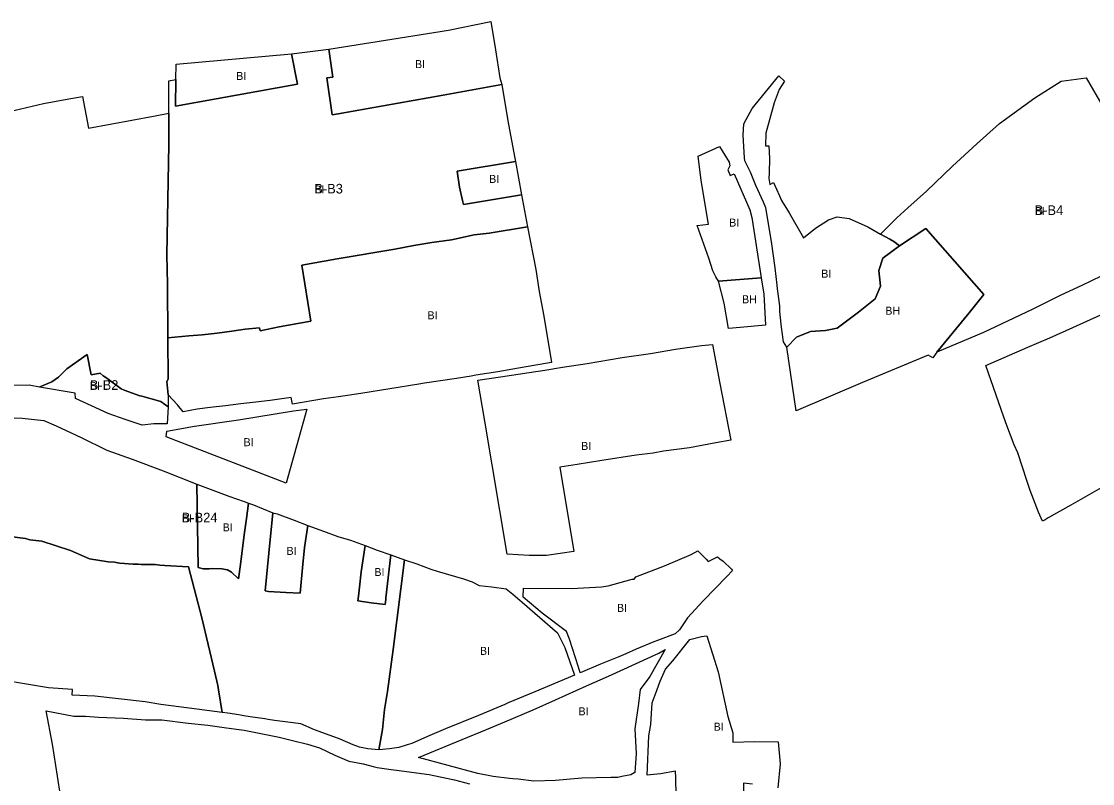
# Model space of a CAD drawing. Extents: x -532081 to -530154, y -1179372 to -1177675.
# Drawn here: x -531512 to -530843, y -1178449 to -1177973 of the extents above; entities that cross this region are included whole.
import ezdxf

# ---------------------------------------------------------------- set-up
doc = ezdxf.new("R2010")
doc.units = 0
for name, color, linetype in [('90030013', 7, 'Continuous'), ('90040013', 7, 'Continuous'), ('90040023', 7, 'Continuous'), ('ID_navrh', 7, 'Continuous')]:
    doc.layers.add(name, color=color, linetype=linetype)

msp = doc.modelspace()

# ---------------------------------------------------------------- linework, layer by layer
at = {"layer": '90030013'}
for points in [[(-530940.69, -1178179.99), (-530943.19, -1178183.38), (-530946.02, -1178181.86), (-530987.13, -1178198.87), (-531028.46, -1178216.55), (-531034.33, -1178176.84), (-531028.24, -1178170.51), (-531019.54, -1178167.02), (-531010.19, -1178166.36), (-531002.79, -1178164.84), (-530989.52, -1178155.02), (-530979.08, -1178146.51), (-530975.82, -1178138.65), (-530976.9, -1178128.84), (-530974.29, -1178121.2), (-530964.07, -1178113.56), (-530947.55, -1178102.59), (-530911.33, -1178143.87), (-530920.54, -1178155.27)], [(-531063.56, -1178164.47), (-531070.77, -1178165.22), (-531073.51, -1178149.25), (-531076.99, -1178135.52), (-531050.37, -1178133.53), (-531048.63, -1178143.76), (-531047.64, -1178162.97)]]:
    msp.add_lwpolyline(points, close=True, dxfattribs=at)
at = {"layer": '90040013'}
for points in [[(-531314.55, -1178030.95), (-531318.27, -1178031.65), (-531321.52, -1178008.57), (-531317.8, -1178008.1), (-531320.29, -1177990.65), (-531245.56, -1177978.75), (-531219.08, -1177973.32), (-531216.25, -1177991.09), (-531213.46, -1178008.57), (-531212.3, -1178012.77), (-531249.01, -1178019.29)], [(-531340, -1178012.46), (-531416.2, -1178026.25), (-531415.9, -1178009.61), (-531415.73, -1178000.11), (-531343.72, -1177993.52)], [(-531047.51, -1178043.09), (-531047.61, -1178051.11), (-531045.49, -1178051.08), (-531045.12, -1178058.95), (-531045.42, -1178067.91), (-531045.62, -1178071.43), (-531044.84, -1178075.23), (-531042.7, -1178073.96), (-531038.81, -1178082.36), (-531037.65, -1178085.28), (-531032.88, -1178092.84), (-531023.96, -1178108.41), (-531016.41, -1178102.47), (-531008.24, -1178097.35), (-531002.97, -1178095.44), (-530995.34, -1178096.38), (-530983.8, -1178101.69), (-530975.85, -1178106.23), (-530970.09, -1178109.35), (-530967.59, -1178110.76), (-530964.07, -1178113.56), (-530974.29, -1178121.2), (-530976.9, -1178128.84), (-530975.82, -1178138.65), (-530979.08, -1178146.51), (-530989.52, -1178155.02), (-531002.79, -1178164.84), (-531010.19, -1178166.36), (-531019.54, -1178167.02), (-531028.24, -1178170.51), (-531034.33, -1178176.84), (-531036.44, -1178173.56), (-531037.6, -1178164.36), (-531038.58, -1178156.56), (-531038.78, -1178154.31), (-531038.78, -1178150.9), (-531040.12, -1178140.3), (-531040.42, -1178138.03), (-531041.56, -1178127.32), (-531044, -1178110.86), (-531047.37, -1178089.86), (-531048.96, -1178086.17), (-531053.71, -1178075.8), (-531057, -1178067.52), (-531060.55, -1178060.44), (-531060.8, -1178058.57), (-531061.6, -1178044.47), (-531061.1, -1178037.26), (-531059.71, -1178034.6), (-531055.92, -1178027.65), (-531045.83, -1178015.25), (-531039.28, -1178007.28), (-531035.87, -1178010.69), (-531039.02, -1178015.75), (-531042.3, -1178024.23)], [(-531071.08, -1178066.04), (-531069.67, -1178069.64), (-531067.12, -1178068.49), (-531057.38, -1178091.05), (-531056.14, -1178095.84), (-531050.37, -1178133.53), (-531076.99, -1178135.52), (-531078.73, -1178132.78), (-531080.48, -1178129.04), (-531082.96, -1178121.3), (-531090.3, -1178100.75), (-531083.23, -1178099.93), (-531087.83, -1178072.76), (-531089.78, -1178057.48), (-531076.33, -1178051.44), (-531070.31, -1178061.21), (-531069.95, -1178063.52)], [(-531200.05, -1178081.65), (-531236.34, -1178087.62), (-531236.93, -1178085.23), (-531238.79, -1178076.87), (-531240.18, -1178066.85), (-531203.7, -1178060.79)], [(-531186.1, -1178157.45), (-531181.32, -1178186.45), (-531192.34, -1178188.32), (-531205.44, -1178190.62), (-531214.8, -1178192.29), (-531228.52, -1178194.37), (-531231.45, -1178194.83), (-531240.72, -1178196.29), (-531260.61, -1178199.33), (-531264.22, -1178199.81), (-531300.31, -1178205.64), (-531314.32, -1178207.81), (-531323.59, -1178209), (-531343.04, -1178212.43), (-531343.78, -1178208.28), (-531356.91, -1178210.06), (-531365.91, -1178211.09), (-531375.21, -1178212.28), (-531384.8, -1178213.46), (-531394.39, -1178214.5), (-531402.65, -1178215.53), (-531411.34, -1178217.15), (-531414.85, -1178212.88), (-531420.59, -1178206.53), (-531421.5, -1178198.3), (-531420.59, -1178196.78), (-531420.85, -1178170.95), (-531407.82, -1178169.8), (-531399.4, -1178169.06), (-531390.11, -1178168.02), (-531380.96, -1178166.84), (-531372.55, -1178165.65), (-531363.55, -1178164.62), (-531363.25, -1178166.54), (-531351.45, -1178164.03), (-531331.59, -1178160.46), (-531337.18, -1178125.51), (-531315.16, -1178121.63), (-531279.17, -1178115.66), (-531267.27, -1178113.28), (-531255.97, -1178111.49), (-531243.78, -1178109.7), (-531229.5, -1178106.71), (-531220.28, -1178105.52), (-531196.18, -1178101.64), (-531191.09, -1178128.25), (-531189.05, -1178142.11)], [(-531184.5, -1178306.91), (-531195.33, -1178306.91), (-531208.88, -1178306.09), (-531222.97, -1178223.05), (-531227.38, -1178197.43), (-531213.12, -1178195.28), (-531195.19, -1178192.59), (-531185.51, -1178191.14), (-531174.38, -1178189.28), (-531158.92, -1178187.01), (-531137.08, -1178183.29), (-531119.56, -1178180.84), (-531103.93, -1178178.12), (-531087.69, -1178175.71), (-531080.77, -1178175.11), (-531076.26, -1178199.54), (-531069.39, -1178234.83), (-531078.67, -1178236.63), (-531095.21, -1178239.65), (-531111.44, -1178241.76), (-531117.76, -1178242.97), (-531128.42, -1178244.27), (-531149.86, -1178247.58), (-531165.31, -1178250.06), (-531176.03, -1178251.71), (-531167.37, -1178304.49)], [(-531334.11, -1178215.48), (-531347.04, -1178261.81), (-531421.87, -1178232.71), (-531421.5, -1178229.19), (-531404.32, -1178226.23), (-531376.79, -1178222.15), (-531342.42, -1178216.59)], [(-531375.58, -1178312.48), (-531376.73, -1178321.53), (-531381.14, -1178317.29), (-531383.64, -1178315.94), (-531387.09, -1178315.17), (-531392.85, -1178314.98), (-531395.15, -1178315.17), (-531398.8, -1178315.17), (-531401.87, -1178314.4), (-531402.8, -1178262.41), (-531382.89, -1178269.79), (-531373.28, -1178273.28), (-531370.51, -1178274.28), (-531371.77, -1178283.83), (-531373.25, -1178294.08)], [(-531336.82, -1178314.57), (-531338.22, -1178330.44), (-531347.22, -1178329.95), (-531358.05, -1178329.37), (-531360.06, -1178328.96), (-531357.85, -1178305.54), (-531355.27, -1178280.22), (-531352.58, -1178280.94), (-531342.01, -1178284.94), (-531333.5, -1178288.29), (-531335.45, -1178301.87)], [(-531284.77, -1178334.39), (-531285.13, -1178337.5), (-531293.84, -1178336.4), (-531302.28, -1178335.34), (-531301.91, -1178332.41), (-531301.19, -1178326.71), (-531300.24, -1178317.22), (-531297.65, -1178300.79), (-531290.09, -1178303.52), (-531281.54, -1178306.45), (-531284.65, -1178333.35)], [(-531084.74, -1178309.14), (-531083.47, -1178310.62), (-531077.57, -1178307.87), (-531076.19, -1178309.03), (-531074.09, -1178310.5), (-531068.92, -1178315.49), (-531068.18, -1178316.33), (-531071.87, -1178320.14), (-531086.52, -1178335.3), (-531096.26, -1178345.93), (-531101.36, -1178353.44), (-531104.08, -1178355.94), (-531115.05, -1178359.94), (-531117.31, -1178360.85), (-531128.37, -1178365.37), (-531134.91, -1178368.32), (-531139.17, -1178370.13), (-531150.72, -1178374.88), (-531163.36, -1178380.32), (-531164.5, -1178376.63), (-531170.14, -1178359.24), (-531171.94, -1178354.51), (-531187.06, -1178342.96), (-531199.03, -1178332.99), (-531198.8, -1178327.33), (-531168.78, -1178327.56), (-531150.04, -1178326.43), (-531145.98, -1178325.97), (-531130.85, -1178321.67), (-531129.72, -1178321.67), (-531128.6, -1178320.19), (-531110.66, -1178313.36), (-531094.09, -1178306.3), (-531089.89, -1178303.97), (-531087.16, -1178306.71)], [(-531282.42, -1178427.76), (-531289.19, -1178428.36), (-531286.77, -1178415.6), (-531285.6, -1178403.11), (-531283.65, -1178391.83), (-531280.15, -1178365.55), (-531273.03, -1178309.63), (-531265.44, -1178312.07), (-531256.62, -1178315.42), (-531252.67, -1178316.64), (-531236.26, -1178321.52), (-531230.87, -1178323.48), (-531226.54, -1178325.74), (-531218.53, -1178326.54), (-531209.55, -1178327.67), (-531205.54, -1178331.04), (-531199.61, -1178336.03), (-531177.64, -1178355.17), (-531172.99, -1178364.34), (-531166.85, -1178381.63), (-531191.8, -1178392.03), (-531208.33, -1178398.97), (-531210.43, -1178400.02), (-531226.96, -1178406.81), (-531247.55, -1178415.25), (-531258.83, -1178419.92), (-531268.6, -1178424.44), (-531271.45, -1178425.2), (-531276.71, -1178426.86)], [(-531178.71, -1178447.38), (-531192.41, -1178447.87), (-531202.07, -1178446.74), (-531205.35, -1178446.38), (-531207.45, -1178446.2), (-531217.65, -1178444.97), (-531227.32, -1178443.03), (-531264.42, -1178433.15), (-531236.99, -1178421.87), (-531221.87, -1178415.69), (-531210.44, -1178410.76), (-531192.69, -1178403.35), (-531178.8, -1178397), (-531159.46, -1178388.36), (-531145.8, -1178382.3), (-531114.35, -1178367.93), (-531110.33, -1178365.65), (-531119.85, -1178382.49), (-531125.86, -1178390.62), (-531127.03, -1178399.46), (-531129.25, -1178415.19), (-531128.45, -1178430.57), (-531129.32, -1178442.53), (-531131.77, -1178444.02), (-531137.43, -1178444.88), (-531139.79, -1178445.6), (-531144.3, -1178445.6), (-531162.33, -1178446.04)]]:
    msp.add_lwpolyline(points, close=True, dxfattribs=at)
for points in [[(-530836.67, -1178263.93), (-530856.88, -1178275.56), (-530871.1, -1178283.46), (-530873.08, -1178284.56), (-530874.71, -1178285.46), (-530877.24, -1178279.8), (-530882.45, -1178266.31), (-530884.51, -1178260.03), (-530887.11, -1178251.75), (-530890.15, -1178242.82), (-530892.32, -1178237.81), (-530896.89, -1178225.83), (-530898.84, -1178220.6), (-530909.99, -1178188.17), (-530883.85, -1178176.76), (-530870.12, -1178170.95), (-530855.76, -1178164.5), (-530829.59, -1178152.67)], [(-531521.2, -1178294.91), (-531509.87, -1178296.36), (-531507.02, -1178297.08), (-531499.66, -1178298.03), (-531481.6, -1178303.75), (-531469.72, -1178308.99), (-531458.08, -1178310.94), (-531454.25, -1178311.13), (-531450.99, -1178311.71), (-531447.92, -1178311.9), (-531445.42, -1178312.09), (-531442.54, -1178312.29), (-531439.47, -1178312.29), (-531437.55, -1178312.48), (-531428.73, -1178312.48), (-531425.85, -1178313.06), (-531422.78, -1178313.25), (-531408.01, -1178314.02), (-531399.61, -1178345.92), (-531391.66, -1178379.21), (-531389.75, -1178388.11), (-531389.15, -1178390.91), (-531386.89, -1178405.1), (-531402.87, -1178402.95), (-531425.26, -1178400.02), (-531435, -1178398.26), (-531466.55, -1178394.88), (-531480.61, -1178394.11), (-531480.42, -1178390.54), (-531495.46, -1178389.57), (-531509.09, -1178387.21), (-531538.87, -1178382.3)], [(-531103.5, -1178456.96), (-531103.74, -1178445.71), (-531103.83, -1178441.67), (-531113.16, -1178443.25), (-531121.45, -1178444.12), (-531120.59, -1178419.51), (-531119.31, -1178412.48), (-531118.33, -1178398.92), (-531115.4, -1178390.71), (-531113.47, -1178385.45), (-531110.15, -1178377.92), (-531105.56, -1178372.73), (-531094.85, -1178359.38), (-531087.59, -1178357.48), (-531084.36, -1178357.14), (-531077.13, -1178379.67), (-531071.12, -1178407.45), (-531068.08, -1178417.72), (-531068.08, -1178423.5), (-531054.42, -1178423.14), (-531039.67, -1178423.32), (-531038.59, -1178437.02), (-531040.03, -1178451.99)], [(-531486.01, -1178469.03), (-531489.73, -1178444.75), (-531493.02, -1178424.7), (-531496.88, -1178403.97), (-531479.56, -1178407.31), (-531472.23, -1178407.31), (-531464.23, -1178407.98), (-531448.58, -1178408.64), (-531434.92, -1178409.65), (-531424.59, -1178409.65), (-531408.27, -1178411.65), (-531395.94, -1178412.99), (-531384.28, -1178414.66), (-531373.29, -1178416), (-531351.3, -1178420.34), (-531342.31, -1178422.68), (-531333.58, -1178424.76), (-531326.19, -1178427.1), (-531316.67, -1178431.58), (-531307.92, -1178435.48), (-531298.98, -1178437.04), (-531294.9, -1178438.01), (-531292.57, -1178438.7), (-531290.24, -1178439.38), (-531281.49, -1178440.55), (-531277.99, -1178441.13), (-531257.78, -1178443.67), (-531254.86, -1178444.45), (-531241.84, -1178446.98), (-531232.53, -1178449.47)], [(-531055.86, -1178449.83), (-531061.44, -1178449.1), (-531061.44, -1178461.19)]]:
    msp.add_lwpolyline(points, dxfattribs=at)
at = {"layer": '90040023'}
for points in [[(-531212.3, -1178012.77), (-531208.58, -1178035.38), (-531204.39, -1178057.76), (-531203.7, -1178060.79), (-531240.18, -1178066.85), (-531238.79, -1178076.87), (-531236.93, -1178085.23), (-531236.34, -1178087.62), (-531200.05, -1178081.65), (-531196.18, -1178101.64), (-531220.28, -1178105.52), (-531229.5, -1178106.71), (-531243.78, -1178109.7), (-531255.97, -1178111.49), (-531267.27, -1178113.28), (-531279.17, -1178115.66), (-531315.16, -1178121.63), (-531337.18, -1178125.51), (-531331.59, -1178160.46), (-531351.45, -1178164.03), (-531363.25, -1178166.54), (-531363.55, -1178164.62), (-531372.55, -1178165.65), (-531380.96, -1178166.84), (-531390.11, -1178168.02), (-531399.4, -1178169.06), (-531407.82, -1178169.8), (-531420.85, -1178170.95), (-531421.2, -1178137.39), (-531421.5, -1178119.11), (-531421.2, -1178095.96), (-531420.36, -1178050.29), (-531420.36, -1178030.73), (-531420.36, -1178010.41), (-531415.9, -1178009.61), (-531416.2, -1178026.25), (-531340, -1178012.46), (-531343.72, -1177993.52), (-531320.29, -1177990.65), (-531317.8, -1178008.1), (-531321.52, -1178008.57), (-531318.27, -1178031.65), (-531314.55, -1178030.95), (-531249.01, -1178019.29)], [(-531468.5, -1178213.35), (-531478.54, -1178208.89), (-531478.69, -1178205.44), (-531500.95, -1178201.68), (-531500.78, -1178201.61), (-531493.36, -1178198.45), (-531489.14, -1178195.45), (-531484.05, -1178190.34), (-531471.22, -1178181.35), (-531468.76, -1178194.04), (-531463.13, -1178192.99), (-531461.2, -1178194.75), (-531458.92, -1178196.16), (-531450.13, -1178202.86), (-531448.19, -1178203.74), (-531438.35, -1178207.27), (-531437.12, -1178207.44), (-531425.17, -1178210.79), (-531420.59, -1178214.14), (-531421.22, -1178224.6), (-531429.69, -1178224.6), (-531436.93, -1178225.56), (-531447.62, -1178221.93), (-531458.14, -1178218.13)]]:
    msp.add_lwpolyline(points, close=True, dxfattribs=at)
for points in [[(-530838.02, -1178132.49), (-530850.01, -1178138.21), (-530863.19, -1178144.33), (-530881.08, -1178153.2), (-530911.56, -1178167.6), (-530940.69, -1178179.99), (-530920.54, -1178155.27), (-530911.33, -1178143.87), (-530947.55, -1178102.59), (-530964.07, -1178113.56), (-530967.59, -1178110.76), (-530970.09, -1178109.35), (-530975.85, -1178106.23), (-530965.53, -1178095.94), (-530958.74, -1178089.84), (-530947.06, -1178079.34), (-530930.83, -1178063.69), (-530915.71, -1178049.72), (-530901.45, -1178037.12), (-530879.38, -1178021.11), (-530863.09, -1178010.55), (-530847.41, -1178008.47), (-530836.83, -1178026.85)], [(-531526.97, -1178031.35), (-531498.44, -1178024.68), (-531482.65, -1178021.63), (-531474.25, -1178020.22), (-531470.54, -1178040.04), (-531429.76, -1178032.41), (-531420.36, -1178030.73), (-531420.36, -1178050.29), (-531421.2, -1178095.96), (-531421.5, -1178119.11), (-531421.2, -1178137.39), (-531420.85, -1178170.95), (-531420.59, -1178196.78), (-531421.5, -1178198.3), (-531420.59, -1178206.53), (-531420.59, -1178214.14), (-531425.17, -1178210.79), (-531437.12, -1178207.44), (-531438.35, -1178207.27), (-531448.19, -1178203.74), (-531450.13, -1178202.86), (-531458.92, -1178196.16), (-531461.2, -1178194.75), (-531463.13, -1178192.99), (-531468.76, -1178194.04), (-531471.22, -1178181.35), (-531484.05, -1178190.34), (-531489.14, -1178195.45), (-531493.36, -1178198.45), (-531500.78, -1178201.61), (-531500.95, -1178201.68), (-531507.5, -1178200.57), (-531520.9, -1178200.8)], [(-531532.26, -1178220.41), (-531511.78, -1178221.23), (-531498.39, -1178222.65), (-531490.73, -1178225.9), (-531475.11, -1178233.23), (-531458.89, -1178241.16), (-531443.07, -1178246.85), (-531423.78, -1178253.96), (-531402.8, -1178262.41), (-531401.87, -1178314.4), (-531398.8, -1178315.17), (-531395.15, -1178315.17), (-531392.85, -1178314.98), (-531387.09, -1178315.17), (-531383.64, -1178315.94), (-531381.14, -1178317.29), (-531376.73, -1178321.53), (-531375.58, -1178312.48), (-531373.25, -1178294.08), (-531371.77, -1178283.83), (-531370.51, -1178274.28), (-531367.46, -1178275.36), (-531355.27, -1178280.22), (-531357.85, -1178305.54), (-531360.06, -1178328.96), (-531358.05, -1178329.37), (-531347.22, -1178329.95), (-531338.22, -1178330.44), (-531336.82, -1178314.57), (-531335.45, -1178301.87), (-531333.5, -1178288.29), (-531323.78, -1178291.65), (-531314.66, -1178295), (-531306.76, -1178297.44), (-531297.65, -1178300.79), (-531300.24, -1178317.22), (-531301.19, -1178326.71), (-531301.91, -1178332.41), (-531302.28, -1178335.34), (-531293.84, -1178336.4), (-531285.13, -1178337.5), (-531284.77, -1178334.39), (-531284.65, -1178333.35), (-531281.54, -1178306.45), (-531273.03, -1178309.63), (-531280.15, -1178365.55), (-531283.65, -1178391.83), (-531285.6, -1178403.11), (-531286.77, -1178415.6), (-531289.19, -1178428.36), (-531295.93, -1178427.78), (-531301.1, -1178426.66), (-531305.15, -1178425.3), (-531313.24, -1178421.69), (-531321.79, -1178418.54), (-531329.2, -1178415.91), (-531337.92, -1178412.05), (-531345.86, -1178411.02), (-531354.32, -1178410), (-531358.26, -1178409.4), (-531360.41, -1178409.01), (-531369.56, -1178407.64), (-531373.46, -1178407.05), (-531376.57, -1178406.47), (-531383.39, -1178405.49), (-531386.89, -1178405.1), (-531389.15, -1178390.91), (-531389.75, -1178388.11), (-531391.66, -1178379.21), (-531399.61, -1178345.92), (-531408.01, -1178314.02), (-531422.78, -1178313.25), (-531425.85, -1178313.06), (-531428.73, -1178312.48), (-531437.55, -1178312.48), (-531439.47, -1178312.29), (-531442.54, -1178312.29), (-531445.42, -1178312.09), (-531447.92, -1178311.9), (-531450.99, -1178311.71), (-531454.25, -1178311.13), (-531458.08, -1178310.94), (-531469.72, -1178308.99), (-531481.6, -1178303.75), (-531499.66, -1178298.03), (-531507.02, -1178297.08), (-531509.87, -1178296.36), (-531521.2, -1178294.91)]]:
    msp.add_lwpolyline(points, dxfattribs=at)

# ---------------------------------------------------------------- texts
at = {"layer": '90030013'}
for p in [(-531062.31, -1178149.39), (-530972.83, -1178156.53)]:
    msp.add_text('BH', height=5, rotation=360, dxfattribs=at).set_placement(p)
at = {"layer": '90040013'}
for rotation, p in [(0, (-531266.52, -1178002.48)), (0, (-531378.21, -1178009.89)), (0, (-531220.26, -1178074.2)), (360, (-531070.34, -1178101.48)), (360, (-531012.84, -1178133.39)), (0, (-531258.77, -1178159.39)), (360, (-531373.6, -1178238.64)), (0, (-531162.79, -1178241.01)), (360, (-531386.65, -1178291.83)), (360, (-531346.78, -1178306.56)), (0, (-531291.91, -1178319.75)), (0, (-531140.41, -1178342.15)), (360, (-531225.97, -1178369)), (0, (-531164.46, -1178406.76)), (0, (-531080.02, -1178416.39))]:
    msp.add_text('BI', height=5, rotation=rotation, dxfattribs=at).set_placement(p)
at = {"layer": '90040023'}
for rotation, p in [(0, (-531329.42, -1178080.8)), (360, (-530879.56, -1178094.23)), (0, (-531469.63, -1178203.45)), (360, (-531412.18, -1178286.22))]:
    msp.add_text('BI', height=5, rotation=rotation, dxfattribs=at).set_placement(p)
at = {"layer": 'ID_navrh'}
for s, rotation, p in [('B-B3', 0, (-531329.42, -1178080.8)), ('B-B4', 0, (-530879.56, -1178094.23)), ('B-B2', 360, (-531469.63, -1178203.45)), ('B-B24', 360, (-531412.18, -1178286.22))]:
    msp.add_text(s, height=6, rotation=rotation, dxfattribs=at).set_placement(p)

doc.saveas('drawing.dxf')
